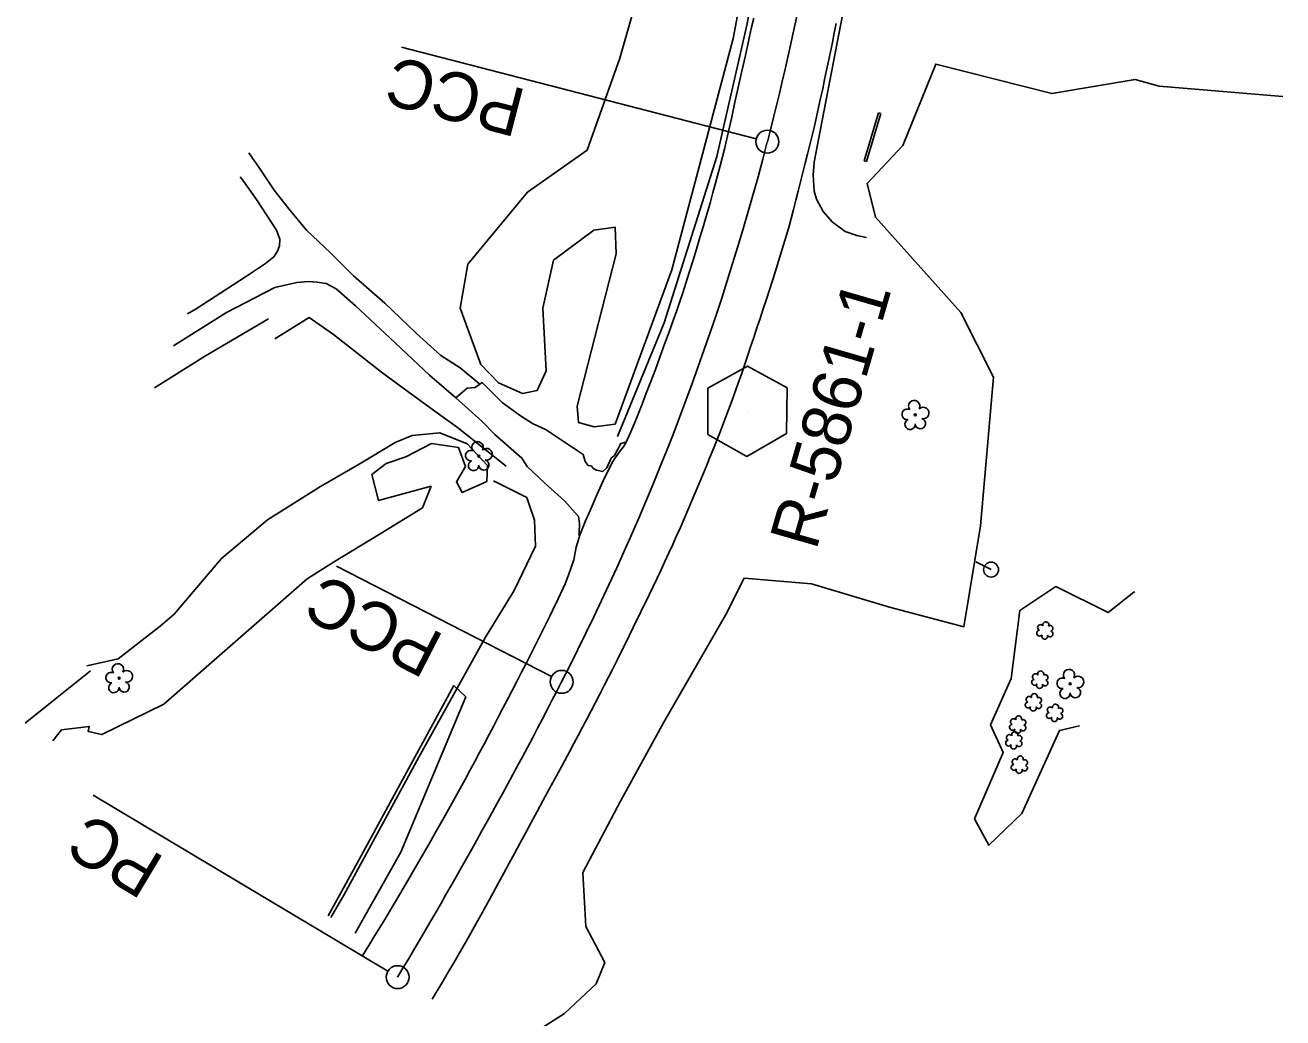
# Model space of a CAD drawing. Extents: x 479429 to 482809, y 488118 to 492379.
# Drawn here: x 480933.9 to 481346, y 489130.7 to 489456.1 of the extents above; entities that cross this region are included whole.
import ezdxf

# ---------------------------------------------------------------- set-up
doc = ezdxf.new("R2010")
doc.units = 0
for name, color, linetype in [('CTL Primary Horizontal and Vertical CELL', 7, 'Continuous'), ('CTL Primary Horizontal and Vertical Text', 7, 'Continuous'), ('Exist Guardrail', 7, 'Continuous'), ('Exist Horizontal Alignment', 7, 'Continuous'), ('Exist Other Culture Fence Line', 7, 'Continuous'), ('Exist Other Culture Gate', 7, 'Continuous'), ('Exist Roads EOP', 7, 'Continuous'), ('Exist Roads EOP Other', 7, 'Continuous'), ('Exist Roads Soil', 7, 'Continuous'), ('Exist Structure Major Bridge WW', 7, 'Continuous'), ('Exist Structure Minor Head and End Wall', 7, 'Continuous'), ('Exist Utilities Power Pole CELL', 7, 'Continuous'), ('Exist Vegetation Hedge Row', 7, 'Continuous'), ('Exist Vegetation Shrub CELL', 7, 'Continuous'), ('Exist Vegetation Tree CELL', 7, 'Continuous'), ('Exist Vegetation Woods Line', 7, 'Continuous')]:
    doc.layers.add(name, color=color, linetype=linetype)

msp = doc.modelspace()

# ---------------------------------------------------------------- linework, layer by layer
at = {"layer": 'CTL Primary Horizontal and Vertical CELL'}
msp.add_line((481170.45, 489329.56), (481170.45, 489329.56), dxfattribs=at)
msp.add_lwpolyline([(481157.53, 489337.05), (481170.53, 489344.3), (481183.53, 489337.15), (481183.33, 489322.25), (481170.33, 489314.7), (481157.53, 489321.95)], close=True, dxfattribs=at)
at = {"layer": 'Exist Guardrail'}
for points in [[(481127.93, 489321.27), (481143.27, 489358.47), (481160.51, 489413.03), (481170.35, 489456.09), (481177.9, 489495.17), (481185.25, 489541.39), (481189.95, 489572.74), (481196.12, 489621.29), (481202.28, 489673.59), (481209.04, 489731.3), (481213.58, 489770.37)], [(481243.62, 489767.54), (481234.85, 489692.14), (481226.82, 489624.9), (481218.29, 489557.25), (481207.78, 489491.18), (481193.85, 489418.57), (481192.36, 489411.18), (481192.08, 489406.88), (481192.44, 489401.65), (481193.22, 489399.06), (481195.38, 489394.97), (481198.33, 489391.63), (481202.58, 489388.42), (481206.38, 489387.09), (481209.6, 489386.42)]]:
    msp.add_lwpolyline(points, dxfattribs=at)
at = {"layer": 'Exist Horizontal Alignment'}
for p, q in [((481173.44, 489418.8), (481057.22, 489448.81)), ((481106.34, 489242.54), (481035.94, 489278.72)), ((481052.69, 489145.96), (480956.18, 489203.72))]:
    msp.add_line(p, q, dxfattribs=at)
for centre in [(481177.07, 489417.86), (481109.67, 489240.82), (481055.91, 489144.03)]:
    msp.add_circle(centre, 3.75, dxfattribs=at)
for centre, radius, start, end in [((480215.08, 489666.29), 993.55, 345.52039, 353.03983), ((480349.38, 489631.6), 854.84, 332.7972, 345.52039), ((479583.42, 490025.3), 1716.06, 329.09986, 332.7972)]:
    msp.add_arc(centre, radius, start, end, dxfattribs=at)
at = {"layer": 'Exist Other Culture Fence Line'}
for points in [[(481013.63, 489359.8), (480992.92, 489347.72), (480976.3, 489337.17)], [(481091.53, 489311.5), (481075.52, 489324.17), (481066.57, 489330.6), (481058.08, 489336.86), (481050.62, 489342.34), (481034.87, 489354.7), (481026.96, 489360.3)], [(481084.73, 489255.5), (481094.15, 489270.8), (481101.05, 489285.32), (481100.8, 489293.77), (481098.86, 489299.58), (481098.3, 489301.21)], [(481034.08, 489163.53), (481038.26, 489170.9), (481062.9, 489216.18), (481084.73, 489255.5)]]:
    msp.add_lwpolyline(points, dxfattribs=at)
at = {"layer": 'Exist Other Culture Gate'}
for p, q in [((481015.67, 489353.21), (481026.96, 489360.3)), ((481098.3, 489301.21), (481087.29, 489306.74))]:
    msp.add_line(p, q, dxfattribs=at)
at = {"layer": 'Exist Roads EOP'}
for points in [[(481044.55, 489151.21), (481046.85, 489154.97), (481048.49, 489157.67), (481050.11, 489160.34), (481051.7, 489162.97), (481053.26, 489165.57), (481054.86, 489168.27), (481056.6, 489171.19), (481058.46, 489174.35), (481060.45, 489177.74), (481062.46, 489181.19), (481064.4, 489184.54), (481066.27, 489187.78), (481068.06, 489190.92), (481069.8, 489193.98), (481071.5, 489197.01), (481073.17, 489200), (481074.8, 489202.95), (481076.41, 489205.89), (481078.01, 489208.83), (481079.61, 489211.79), (481081.21, 489214.75), (481082.79, 489217.7), (481084.35, 489220.63), (481085.88, 489223.53), (481087.4, 489226.4), (481088.9, 489229.27), (481090.41, 489232.15), (481091.93, 489235.05), (481093.45, 489237.97), (481094.97, 489240.89), (481096.46, 489243.79), (481097.94, 489246.66), (481099.4, 489249.5), (481100.81, 489252.28), (481103.45, 489257.53), (481105.8, 489262.31), (481106.82, 489264.41), (481108.53, 489268.01), (481110.81, 489272.99), (481112.08, 489276.17), (481113.66, 489280.85), (481114.39, 489284.99), (481115.7, 489289.2), (481117.46, 489293.56), (481118.97, 489297), (481121.33, 489302.37), (481123.72, 489307.68), (481126.43, 489313.03), (481128.49, 489316.14), (481129.79, 489317.75), (481130.55, 489318.91), (481132.34, 489322.78), (481133.82, 489326.35), (481136.01, 489331.87), (481137.39, 489335.4), (481138.87, 489339.25), (481140.37, 489343.22), (481141.88, 489347.29), (481143.42, 489351.48), (481144.89, 489355.54), (481146.2, 489359.22), (481147.36, 489362.53), (481148.37, 489365.47), (481149.34, 489368.36), (481150.37, 489371.53), (481151.47, 489374.99), (481152.64, 489378.73), (481153.83, 489382.61), (481154.99, 489386.46), (481156.13, 489390.29), (481157.24, 489394.1), (481158.29, 489397.77), (481159.25, 489401.17), (481160.12, 489404.33), (481161.62, 489409.98), (481162.98, 489415.42), (481164.25, 489420.75), (481165.41, 489425.87), (481166.46, 489430.78), (481167.52, 489435.61), (481168.61, 489440.51), (481169.86, 489446.09), (481170.55, 489449.18), (481171.25, 489452.32), (481171.93, 489455.39), (481172.6, 489458.38)], [(481199.65, 489456.65), (481199.02, 489453.52), (481198.39, 489450.43), (481197.76, 489447.36), (481197.13, 489444.32), (481196.49, 489441.29), (481195.85, 489438.25), (481195.2, 489435.2), (481194.54, 489432.14), (481193.87, 489429.08), (481193.18, 489426.03), (481192.47, 489422.97), (481191.73, 489419.92), (481190.99, 489416.88), (481190.24, 489413.83), (481189.49, 489410.79), (481188.74, 489407.75), (481187.98, 489404.71), (481187.21, 489401.69), (481186.44, 489398.67), (481185.66, 489395.67), (481184.87, 489392.69), (481184.06, 489389.77), (481182.41, 489384.1), (481180.65, 489378.4), (481179.72, 489375.45), (481178.75, 489372.43), (481177.76, 489369.36), (481176.76, 489366.26), (481175.74, 489363.13), (481174.7, 489359.96), (481173.66, 489356.81), (481172.63, 489353.69), (481171.6, 489350.61), (481170.58, 489347.57), (481169.57, 489344.58), (481168.55, 489341.64), (481167.54, 489338.75), (481165.52, 489333.14), (481163.49, 489327.71), (481161.45, 489322.41), (481159.28, 489316.94), (481158.14, 489314.13), (481156.98, 489311.29), (481155.81, 489308.45), (481154.63, 489305.61), (481153.44, 489302.77), (481152.25, 489299.94), (481151.04, 489297.11), (481149.82, 489294.28), (481148.58, 489291.47), (481147.33, 489288.66), (481146.08, 489285.86), (481144.8, 489283.08), (481143.52, 489280.31), (481142.23, 489277.55), (481140.93, 489274.8), (481139.63, 489272.07), (481138.33, 489269.35), (481135.74, 489263.96), (481133.16, 489258.66), (481130.55, 489253.35), (481129.21, 489250.64), (481127.85, 489247.89), (481126.47, 489245.13), (481125.06, 489242.36), (481123.64, 489239.58), (481122.21, 489236.8), (481120.77, 489234.03), (481119.34, 489231.3), (481117.92, 489228.61), (481116.52, 489225.95), (481115.1, 489223.29), (481113.67, 489220.59), (481112.2, 489217.86), (481110.71, 489215.09), (481109.15, 489212.18), (481107.44, 489209.03), (481105.6, 489205.63), (481103.63, 489201.99), (481101.63, 489198.29), (481099.69, 489194.7), (481097.82, 489191.23), (481096.02, 489187.88), (481094.26, 489184.6), (481092.5, 489181.34), (481090.75, 489178.12), (481089.01, 489174.92), (481087.25, 489171.71), (481085.46, 489168.46), (481083.63, 489165.16), (481081.77, 489161.82), (481079.9, 489158.49), (481078.04, 489155.19), (481076.18, 489151.95), (481074.34, 489148.76), (481072.52, 489145.62), (481070.71, 489142.56), (481068.92, 489139.57), (481067.27, 489136.85)]]:
    msp.add_lwpolyline(points, dxfattribs=at)
at = {"layer": 'Exist Roads EOP Other'}
msp.add_lwpolyline([(481115.34, 489288.93), (481115.45, 489289.53), (481115.52, 489292.68), (481115.24, 489295.07), (481110.6, 489300.18), (481104.04, 489306.05), (481098.41, 489311.38), (481096.67, 489314.16), (481087.82, 489321.88), (481083.48, 489326.32), (481075.04, 489333.94), (481078.74, 489337.09), (481081.38, 489337.31), (481082.81, 489338.43), (481083.6, 489338.89), (481090.16, 489332.36), (481096.18, 489328), (481100.14, 489325.54), (481104.6, 489323.48), (481110.12, 489319.73), (481116.67, 489315.36), (481117.4, 489313.01), (481118.38, 489311.73), (481119.29, 489311.67), (481120.13, 489310.7), (481121.1, 489310.2), (481123.17, 489309.81), (481124.47, 489311), (481125.93, 489314.16), (481127.01, 489315.05), (481129.03, 489318.94), (481130.75, 489319.41)], dxfattribs=at)
at = {"layer": 'Exist Roads Soil'}
for points in [[(481007.16, 489414.21), (481010.84, 489408.84), (481015.5, 489401.99), (481020.27, 489395.84), (481026.06, 489388.89), (481033.88, 489381.43), (481041.46, 489373.92), (481051.77, 489364.97), (481062.04, 489355.08), (481070.07, 489347.76), (481076.37, 489343.71), (481082.81, 489338.43)], [(480987.09, 489361.4), (480989.88, 489363.14), (481006.08, 489373.63), (481012.64, 489377.97), (481015.33, 489380.16), (481016.56, 489381.94), (481017.24, 489383.78), (481017.31, 489385.88), (481016.28, 489388.84), (481009.63, 489398.91), (481004.85, 489405.65), (481004.37, 489406.33)], [(481035.83, 489369.68), (481032.56, 489371.4), (481029.57, 489371.84), (481026.68, 489372.05), (481022.85, 489371.69), (481015.71, 489370.06), (480999.82, 489361.88), (480983.72, 489351.77), (480982.44, 489350.96)], [(481075.04, 489333.94), (481066.36, 489341.31), (481055.14, 489351.9), (481042.15, 489364.07), (481035.83, 489369.68)]]:
    msp.add_lwpolyline(points, dxfattribs=at)
at = {"layer": 'Exist Structure Major Bridge WW'}
for p, q in [((481208.78, 489411.62), (481213.45, 489427.34)), ((481209.57, 489411.38), (481214.25, 489427.11))]:
    msp.add_line(p, q, dxfattribs=at)
at = {"layer": 'Exist Structure Minor Head and End Wall'}
for p, q in [((481213.45, 489427.34), (481214.25, 489427.11)), ((481208.78, 489411.62), (481209.57, 489411.38))]:
    msp.add_line(p, q, dxfattribs=at)
at = {"layer": 'Exist Utilities Power Pole CELL'}
for q in [(481245.37, 489280.16), (481250.39, 489277.61)]:
    msp.add_line((481250.39, 489277.61), q, dxfattribs=at)
msp.add_circle((481250.39, 489277.61), 2.45, dxfattribs=at)
at = {"layer": 'Exist Vegetation Hedge Row'}
for points in [[(481180.88, 489531.49), (481165.89, 489451.67), (481145.78, 489375.87), (481127.17, 489325.29), (481120.31, 489324.37), (481115.21, 489325.82), (481114.8, 489331.2), (481127.51, 489381.14), (481127.2, 489389.87), (481120.18, 489388.9), (481107.05, 489379.09), (481103.52, 489363.29), (481104.64, 489342.72), (481101.7, 489336.33), (481096.84, 489335.39), (481088.95, 489338.8), (481083.16, 489344.88), (481076.45, 489363.27), (481078.97, 489377.7), (481098.48, 489401.3), (481118.06, 489415.1), (481128.79, 489445.23), (481139.49, 489482.89)], [(480982.68, 489263.05), (480998.19, 489281.23), (481013.27, 489293.97), (481030.69, 489304.83), (481043.37, 489312.16), (481055.08, 489319.3), (481060.71, 489321.6), (481069.77, 489322.4), (481078.69, 489318.88), (481085.34, 489311.76), (481085.2, 489306.52), (481077.08, 489302.88), (481075.17, 489306.39), (481078.22, 489311.4), (481075.82, 489317.64), (481066.99, 489318.95), (481058.6, 489314.55), (481052.22, 489312.39), (481047.51, 489308.77)], [(481047.51, 489308.77), (481049.7, 489300.26), (481053.26, 489301.26), (481066.87, 489304.96), (481064.09, 489297.82), (481050.26, 489289.3), (481034.95, 489280), (481026.27, 489274.54), (480992.37, 489244.86)], [(480954.04, 489246.08), (480964.39, 489248.33), (480978.14, 489259.07), (480982.68, 489263.05)], [(480933.88, 489227.27), (480944.32, 489235.7), (480955.32, 489244.48)], [(480992.37, 489244.86), (480979.28, 489233.5), (480958.99, 489223.53), (480954.56, 489224.51), (480954.89, 489226.22), (480945.82, 489225.12)], [(481033.16, 489164.11), (481042.71, 489181.4), (481074.33, 489239.59), (481078.26, 489235.88), (481056.95, 489185.04), (481041.99, 489158.49)], [(480945.82, 489225.12), (480942.9, 489221.54)]]:
    msp.add_lwpolyline(points, dxfattribs=at)
at = {"layer": 'Exist Vegetation Shrub CELL'}
for p, q in [((481268.08, 489257.47), (481268.08, 489257.47)), ((481266.42, 489241.36), (481266.42, 489241.36)), ((481264.33, 489233.94), (481264.33, 489233.94)), ((481271.25, 489230.48), (481271.25, 489230.48)), ((481259.2, 489226.64), (481259.2, 489226.64)), ((481257.91, 489221.46), (481257.91, 489221.46)), ((481259.73, 489213.49), (481259.73, 489213.49))]:
    msp.add_line(p, q, dxfattribs=at)
for centre, radius, start, end in [((481268.31, 489259.51), 0.99, 334.8391, 200.4717), ((481266.28, 489256.77), 0.955, 95.1099, 327.9534), ((481266.6, 489258.6), 0.968, 35.8908, 245.4216), ((481267.95, 489255.79), 0.984, 151.2797, 21.387), ((481269.72, 489256.54), 0.937, 204.9913, 73.4601), ((481269.75, 489258.34), 0.929, 284.4567, 126.0861), ((481266.65, 489243.4), 0.99, 334.8391, 200.4717), ((481264.62, 489240.66), 0.955, 95.1099, 327.9534), ((481264.94, 489242.49), 0.968, 35.8908, 245.4216), ((481266.29, 489239.68), 0.984, 151.2797, 21.387), ((481268.06, 489240.43), 0.937, 204.9913, 73.4601), ((481268.09, 489242.23), 0.929, 284.4567, 126.0861), ((481262.85, 489235.07), 0.968, 35.8908, 245.4216), ((481264.56, 489235.98), 0.99, 334.8391, 200.4717), ((481266, 489234.81), 0.929, 284.4567, 126.0861), ((481262.53, 489233.23), 0.955, 95.1099, 327.9534), ((481264.2, 489232.25), 0.984, 151.2797, 21.387), ((481265.97, 489233.01), 0.937, 204.9913, 73.4601), ((481269.77, 489231.6), 0.968, 35.8908, 245.4216), ((481271.48, 489232.52), 0.99, 334.8391, 200.4717), ((481272.93, 489231.35), 0.929, 284.4567, 126.0861), ((481257.72, 489227.77), 0.968, 35.8908, 245.4216), ((481259.43, 489228.68), 0.99, 334.8391, 200.4717), ((481260.87, 489227.51), 0.929, 284.4567, 126.0861), ((481269.45, 489229.77), 0.955, 95.1099, 327.9534), ((481271.13, 489228.79), 0.984, 151.2797, 21.387), ((481272.89, 489229.55), 0.937, 204.9913, 73.4601), ((481256.42, 489222.58), 0.968, 35.8908, 245.4216), ((481257.4, 489225.94), 0.955, 95.1099, 327.9534), ((481258.14, 489223.5), 0.99, 334.8391, 200.4717), ((481259.07, 489224.96), 0.984, 151.2797, 21.387), ((481259.58, 489222.33), 0.929, 284.4567, 126.0861), ((481260.84, 489225.71), 0.937, 204.9913, 73.4601), ((481256.11, 489220.75), 0.955, 95.1099, 327.9534), ((481257.78, 489219.77), 0.984, 151.2797, 21.387), ((481259.54, 489220.53), 0.937, 204.9913, 73.4601), ((481258.25, 489214.61), 0.968, 35.8908, 245.4216), ((481259.96, 489215.53), 0.99, 334.8391, 200.4717), ((481261.4, 489214.36), 0.929, 284.4567, 126.0861), ((481257.93, 489212.78), 0.955, 95.1099, 327.9534), ((481259.6, 489211.8), 0.984, 151.2797, 21.387), ((481261.37, 489212.56), 0.937, 204.9913, 73.4601)]:
    msp.add_arc(centre, radius, start, end, dxfattribs=at)
at = {"layer": 'Exist Vegetation Tree CELL'}
for p, q in [((481225.56, 489328.36), (481225.56, 489328.36)), ((481082.51, 489314.83), (481082.51, 489314.83)), ((480964.65, 489242.06), (480964.65, 489242.06)), ((481276.32, 489240.19), (481276.32, 489240.19))]:
    msp.add_line(p, q, dxfattribs=at)
for centre in [(481225.56, 489328.36), (481082.51, 489314.83), (480964.65, 489242.06), (481276.32, 489240.19)]:
    msp.add_circle(centre, 0.326, dxfattribs=at)
for centre, radius, start, end in [((481222.95, 489328.51), 1.73, 62.6636, 279.3457), ((481225.17, 489331.23), 1.86, 330.1651, 219.7134), ((481228.11, 489328.95), 1.9, 257.1011, 134.1999), ((481223.85, 489325.24), 1.69, 111.5671, 6.231), ((481227.23, 489325.46), 1.7, 181.2822, 74.56), ((481082.12, 489317.71), 1.86, 330.1651, 219.7134), ((481079.9, 489314.99), 1.73, 62.6636, 279.3457), ((481085.06, 489315.42), 1.9, 257.1011, 134.1999), ((481080.8, 489311.71), 1.69, 111.5671, 6.231), ((481084.18, 489311.93), 1.7, 181.2822, 74.56), ((480962.05, 489242.21), 1.73, 62.6636, 279.3457), ((480964.27, 489244.93), 1.86, 330.1651, 219.7134), ((480967.2, 489242.65), 1.9, 257.1011, 134.1999), ((481275.93, 489243.06), 1.86, 330.1651, 219.7134), ((480962.95, 489238.94), 1.69, 111.5671, 6.231), ((480966.33, 489239.16), 1.7, 181.2822, 74.56), ((481273.71, 489240.34), 1.73, 62.6636, 279.3457), ((481278.86, 489240.78), 1.9, 257.1011, 134.1999), ((481274.61, 489237.07), 1.69, 111.5671, 6.231), ((481277.99, 489237.29), 1.7, 181.2822, 74.56)]:
    msp.add_arc(centre, radius, start, end, dxfattribs=at)
at = {"layer": 'Exist Vegetation Woods Line'}
for points in [[(481163.37, 489262.66), (481169.47, 489274.8), (481191.58, 489272.93), (481217.1, 489265.35), (481241.48, 489258.87), (481246.92, 489291.94), (481251.16, 489340.72), (481240.47, 489361.94), (481212.48, 489393.09), (481209.77, 489404.22), (481221.42, 489416.62), (481232.26, 489443.3), (481270.26, 489433.64), (481297.59, 489438.24), (481305.44, 489436.04), (481345.99, 489432.65)], [(481297.45, 489270.31), (481297.12, 489270.25), (481288.8, 489263.55), (481271.56, 489272.03), (481259.81, 489264.22), (481256.93, 489241.96), (481250.24, 489226.68), (481254.32, 489217.67), (481244.99, 489195.88), (481249.65, 489187.28), (481260.47, 489197.68), (481272.77, 489224.9), (481279.31, 489226.42)], [(481097.01, 489123.49), (481110.59, 489132.07), (481121.03, 489141.83), (481123.81, 489148.88), (481117.58, 489160.62), (481116.64, 489178.28), (481128.99, 489201.74), (481143.15, 489227.58), (481163.37, 489262.66)]]:
    msp.add_lwpolyline(points, dxfattribs=at)

# ---------------------------------------------------------------- texts
at = {"layer": 'CTL Primary Horizontal and Vertical Text'}
msp.add_text('R-5861-1', height=16, rotation=73.904, dxfattribs=at).set_placement((481193.05, 489283.61))
at = {"layer": 'Exist Horizontal Alignment'}
for s, rotation, p in [('PCC', 165.5204, (481098.62, 489434.75)), ('PCC', 152.7972, (481071.74, 489255.9)), ('PC', 149.0999, (480980.11, 489182.94))]:
    msp.add_text(s, height=16, rotation=rotation, dxfattribs=at).set_placement(p)

doc.saveas('drawing.dxf')
